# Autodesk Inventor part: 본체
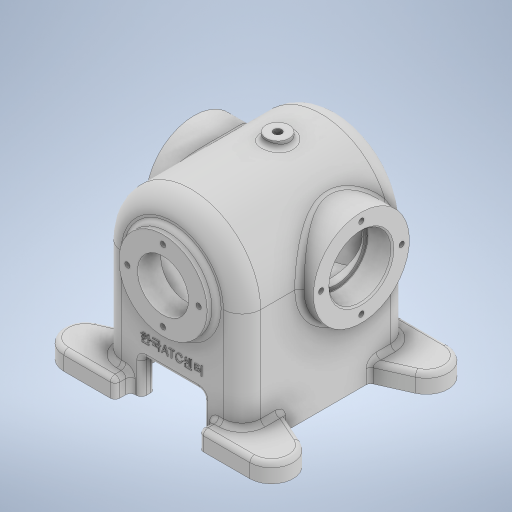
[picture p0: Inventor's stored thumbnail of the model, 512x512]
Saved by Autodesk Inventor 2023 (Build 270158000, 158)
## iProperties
Created: 2024-09
Part Number: 본체
Material: 일반
Document SubType Name: Modeling
Designer: asung
Density: 1 g/cm^3
Appearance: 기본값
Author: asung
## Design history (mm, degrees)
sketch "스케치4"
  geometry: L1 (-45, 0)-(-45, -76); L2 (45, 0)-(45, -76); L3 (0, 0)-(0, -76); L4 (0, -76)-(20, -76); L5 (0, -76)-(-20, -76); L6 (20, -76)-(20, -53); L7 (45, -76)-(20, -76); L8 (-45, -76)-(-20, -76); L9 (-20, -76)-(-20, -53); L10 (-20, -53)-(20, -53); A1 r 45 centre (0, 0) between (-45, 0) and (45, 0); 1 further point
  constraints: 20 end point, 4 vertical, 2 horizontal, 2 point on circle, 1 centre point, 1 coincident, 1 collinear, 1 perpendicular, 1 point on line, 1 tangent
  dimensions: "d14" = 90 diameter of A1; "d15" = 76 distance of L1.start L1.end; "d16" = 76 distance of L2.start L2.end; "d17" = 20 distance of L3.end L4.end; "d18" = 20 distance of L3.end L5.end; "d19" = 23 distance of L4.end L6.end; "d20" = 23 distance of L5.end L9.end
extrude "돌출4" new body sketch "스케치4" distance "d21" = 108; taper "d22" = 0 deg
feature "쉘2" dims "d23" = 9
sketch "스케치5"
  geometry: C1 r 45 at (0, 0); 1 further point
  constraints: 1 centre point, 1 coincident
  dimensions: "d24" = 90 diameter of C1
extrude "돌출5" join sketch "스케치5" distance "d25" = 108; taper "d26" = 0 deg
node "작업 평면1"
sketch "스케치6"
  geometry: C1 r 28.5 at (0, 0); 1 further point
  constraints: 1 centre point, 1 coincident
  dimensions: "d28" = 57 diameter of C1
extrude "돌출6" join sketch "스케치6" distance "d29" = 6; taper "d30" = 0 deg
fillet "모깎기1" dims "d31" = 12
sketch "스케치7"
  geometry: L1 (28.5, 6)-(-28.5, 6) reference; C1 r 31 at (0, -68); 1 further point
  constraints: 1 centre point, 1 vertical alignment
  dimensions: "d32" = 62 diameter of C1; "d33" = 74 distance from line of C1.centre L1
extrude "돌출7" join sketch "스케치7" stored distance "d34" = 6; taper "d35" = 0 deg
sketch "스케치8"
  geometry: C1 r 31 at (0, 0) reference; 2 further points
  constraints: 1 coincident
hole "구멍1" sketch "스케치8" at (0, 0) diameter "d36" = 35; stored, may be unused: countersink angle "d40" = 90 deg, drill point angle "d42" = 118 deg; dims "d37" = 119, "d38" = 40, "d39" = 16, "d41" = 120
sketch "스케치9"
  geometry: C1 r 31 at (0, 0) reference; 2 further points
  constraints: 1 coincident
hole "구멍2" sketch "스케치9" at (0, 0) diameter "d43" = 35; stored, may be unused: countersink angle "d47" = 90 deg, drill point angle "d49" = 118 deg; dims "d44" = 6, "d45" = 40, "d46" = 16, "d48" = 120
node "작업 평면2"
sketch "스케치10"
  geometry: C1 r 37 at (0, 0); 1 further point
  constraints: 1 centre point, 1 coincident
  dimensions: "d51" = 74 diameter of C1
extrude "돌출8" cut sketch "스케치10" distance "d52" = 90; taper "d53" = 0 deg
fillet "모깎기2" dims "d54" = 3
sketch "스케치11" dims "d55" = 52
  geometry: C1 r 20 at (0, 0) reference; C2 r 31 at (0, 0) reference; 3 further points
  constraints: 2 vertical alignment, 1 coincident, 2 other
hole "구멍3" sketch "스케치11" at (0, 26) diameter "d56" = 3.45873; stored, may be unused: countersink angle "d60" = 90 deg, drill point angle "d62" = 118 deg; dims "d57" = 8, "d58" = 40, "d59" = 16, "d61" = 10
sketch "스케치12"
  geometry: C1 r 28.5 at (0, 0) reference; 2 further points
  constraints: 1 coincident
hole "구멍4" sketch "스케치12" at (0, 0) diameter "d66" = 33; stored, may be unused: countersink angle "d70" = 90 deg, drill point angle "d72" = 118 deg; dims "d67" = 8, "d68" = 4, "d69" = 2, "d71" = 50
sketch "스케치13" dims "d74" = 46
  geometry: C1 r 28.5 at (0, 0); 3 further points
  constraints: 2 coincident, 2 vertical alignment, 1 centre point, 2 other
  dimensions: "d73" = 57 diameter of C1
hole "구멍5" sketch "스케치13" at (0, 23) diameter "d75" = 3.45873; stored, may be unused: countersink angle "d79" = 90 deg, drill point angle "d81" = 118 deg; dims "d76" = 8, "d77" = 4, "d78" = 2, "d80" = 10
fillet "모깎기3" dims "d85" = 3
fillet "모깎기4" dims "d86" = 0.3
chamfer "모따기1" distance "d87" = 1; stored, may be unused: second distance "d88" = 2, angle "d89" = 45 deg
node "작업 평면3"
sketch "스케치14"
  geometry: L1 (28.5, 6)-(-28.5, 6) reference; C1 r 7.5 at (0, -68); 1 further point
  constraints: 1 centre point, 1 vertical alignment
  dimensions: "d91" = 15 diameter of C1; "d92" = 74 distance from line of C1.centre L1
extrude "돌출9" join sketch "스케치14" stored distance "d93" = 90; taper "d94" = 0 deg
node "작업 평면4"
sketch "스케치15"
  geometry: L1 (28.5, 6)-(-28.5, 6) reference; C1 r 7.5 at (0, -68); 1 further point
  constraints: 1 centre point, 1 vertical alignment
  dimensions: "d96" = 15 diameter of C1; "d97" = 74 distance from line of C1.centre L1
extrude "돌출10" join sketch "스케치15" stored distance "d98" = 10; taper "d99" = 0 deg
sketch "스케치16"
  geometry: C1 r 7.5 at (0, 0) reference; 2 further points
  constraints: 1 coincident
hole "구멍6" sketch "스케치16" at (0, 0) diameter "d100" = 5.1881; stored, may be unused: countersink angle "d104" = 90 deg, drill point angle "d106" = 118 deg; dims "d101" = 199, "d102" = 4, "d103" = 2, "d105" = 200
fillet "모깎기5" dims "d107" = 3
sketch "스케치17"
  geometry: L1 (13, -99)-(-53, -99) reference; L2 (25, -3)-(25, -87) reference; L3 (40, -95)-(-80, -95); L4 (-80, -95)-(-80, 5); L5 (-80, 5)-(40, 5); L6 (40, 5)-(40, -95); L7 (40, -95)-(-80, 5); L8 (-80, -95)-(40, 5); L9 (-80, -109)-(-47, -109); L10 (-47, -109)-(-47, -95); L11 (-65, -3)-(-65, -87) reference; L12 (-65, -73)-(-85.693, -82.21); L13 (-40, -99)-(-53, -99) reference; L14 (-40, -90)-(-40, -99) reference; L15 (-40, -90)-(-56, -90) reference; L16 (-56, -90)-(-56, 0) reference; L17 (-56, 0)-(-40, 0) reference; L18 (-40, 9)-(-40, 0) reference; L19 (-53, 9)-(-40, 9) reference; L20 (-65, -3)-(-65, -87) reference; A1 r 14 centre (-80, -95) between (-80, -109) and (-85.693, -82.21); A2 r 12 centre (-53, -87) between (-65, -87) and (-53, -99) reference; A3 r 12 centre (-53, -3) between (-53, 9) and (-65, -3) reference; 7 further points
  constraints: 18 end point, 2 horizontal, 2 midpoint, 2 parallel, 2 perpendicular, 2 point on circle, 2 point on line, 2 tangent, 1 centre point, 1 coincident
  dimensions: "d111" = 120 distance of L4.end L5.end; "d112" = 100 distance of L3.end L4.end; "d113" = 15 distance between parallel lines of L2 L6; "d114" = 104 distance between parallel lines of L1 L5; "d115" = 14 radius of A1; "d116" = 18 distance between parallel lines of L11 L10; "d117" = 36 vertical distance of L12.start L9.start
extrude "돌출11" join sketch "스케치17" distance "d118" = 12; taper "d119" = 0 deg
node "작업 평면5"
fillet "모깎기6" dims "d120" = 3
fillet "모깎기7" dims "d121" = 3
fillet "모깎기8" dims "d122" = 3
sketch "스케치18"
  geometry: L1 (60, -76)-(30, -76) reference; 2 further points
  constraints: 1 vertical alignment, 1 other
  dimensions: "d123" = 35 distance from line of L1 point (0, -41)
feature "엠보싱1" sketch "스케치18" dims "d14" = 90, "d15" = 76, "d16" = 76, "d17" = 20, "d18" = 20, "d19" = 23, "d20" = 23, "d124" = 0.5, "d125" = 0
node "솔리드2"
mirror "미러1"
pattern_circular "원형 패턴1" dims angle "d64" = 360 deg
mirror "미러2"
pattern_circular "원형 패턴2" dims angle "d83" = 360 deg
mirror "미러3"
mirror "미러4"
node "투영된 루프2"
node "투영된 루프3"
feature "A9D066F2-1C7D-4E18-AEED-F7BC21143FA4" dims "d36" = 35, "d37" = 119, "d38" = 40, "d39" = 16, "d40" = 90 deg, "d41" = 120, "d42" = 118 deg
other parameters: "d27" = 54, "d50" = -9, "d90" = 49, "d95" = -98
